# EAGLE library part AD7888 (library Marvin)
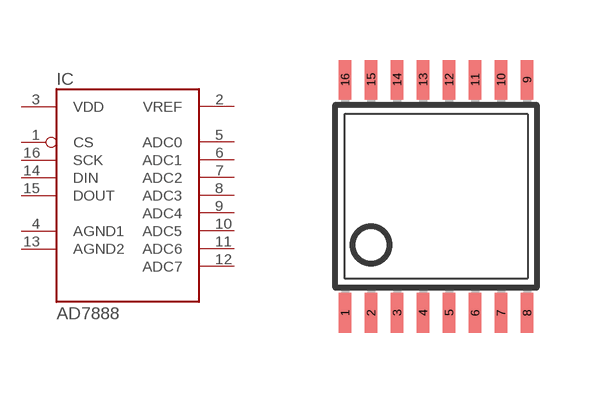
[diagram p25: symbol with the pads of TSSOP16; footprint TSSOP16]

Designator prefix IC

## AD7888  [TSSOP16]
1  CS
2  VREF
3  VDD
4  AGND1
5  ADC0
6  ADC1
7  ADC2
8  ADC3
9  ADC4
10  ADC5
11  ADC6
12  ADC7
13  AGND2
14  DIN
15  DOUT
16  SCK

## Footprint TSSOP16 (pad centres in mm)
smd 0.305 x 0.991: 1 -2.275,-2.918; 2 -1.625,-2.918; 3 -0.975,-2.918; 4 -0.325,-2.918; 5 0.325,-2.918; 6 0.975,-2.918; 7 1.625,-2.918; 8 2.275,-2.918; 9 2.275,2.918; 10 1.625,2.918; 11 0.975,2.918; 12 0.325,2.918; 13 -0.325,2.918; 14 -0.975,2.918; 15 -1.625,2.918; 16 -2.275,2.918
